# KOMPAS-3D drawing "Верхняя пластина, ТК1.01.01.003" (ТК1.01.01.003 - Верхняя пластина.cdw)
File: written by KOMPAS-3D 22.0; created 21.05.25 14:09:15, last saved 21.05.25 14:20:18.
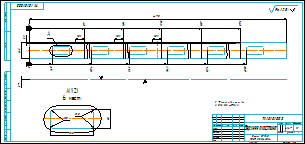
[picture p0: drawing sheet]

Sheet 1: A4x3, landscape

Document properties: Автор: user; Знак неуказанной шероховатости: 4; Параметр неуказанной шероховатости: Ra 12,5; Масса: 41.469866; Форматы листов документа: A4@4~3

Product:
- Part/product: Верхняя пластина  | designation ТК1.01.01.003
    Масса: 41.469866
    Форматы листов документа: A4@4~3

Title block, sheet 1: Наименование: Верхняя пластина; designation: ТК1.01.01.003; Материал: Сталь 09Г2С / ГОСТ 19281-2014; Масса: 41,47; Количество листов документа: 1; Форматы листов документа: A4 3; stored path: D:\Рабочая папка\АРХИВ\612\05\Задание №6 - Тележка для крыши\3Д\Тележка в сборе\Корпус тележки\КД\Верхняя пластина.cdw

Views: Проекционный вид 2, Проекционный вид 3, Выносной элемент 4, Выносной элемент А, Выносной элемент
Referenced files in D:\Рабочая папка\АРХИВ\612\05\Задание №6 - Тележка для крыши\3Д\Тележка в сборе\Корпус тележки\: Верхняя пластина.m3d
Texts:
  Ra 12,5
  Ra 12,5 ( )
  BOSimple***Material:4ccf0190-16b6-4223-9222-aa108d28a442
  ТК1.01.01.003 Верхняя пластина
Dimensions and other numbers on the sheet: 4470; 577; 1431; 2285; 3139; 3993; 101; 168; 5,2; 240; 1094; 1948; 2342; 3196; 4050; 8; 9; 6 мест; 180; 80; 10; 1:1; 1; 41,47

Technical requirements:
  *Размеры для справок.
  H12, h12, ±IT12/2.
